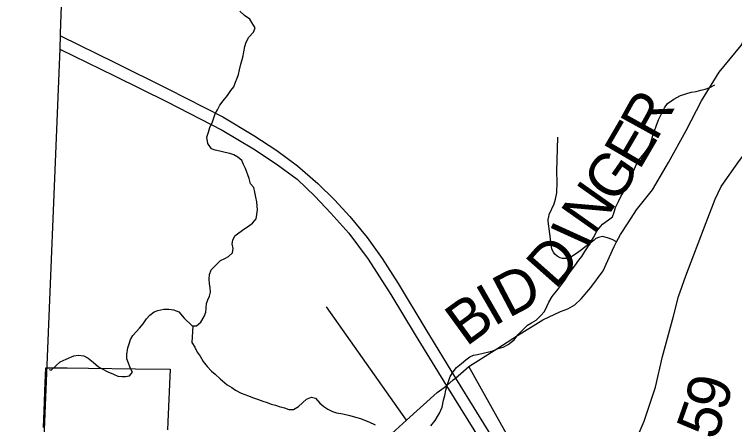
# Model space of a CAD drawing. Extents: x -7.5 to 26.5, y 3.5 to 25.5.
# Drawn here: x -5.222 to -4.268, y 22.72 to 23.263 of the extents above; entities that cross this region are included whole.
import ezdxf

# ---------------------------------------------------------------- set-up
doc = ezdxf.new("R2010")
doc.units = 0
for name, color, linetype in [('GM_X_Corporation', 7, 'Continuous'), ('GM_X_County_Road', 7, 'Continuous'), ('GM_X_County_Road_Text', 7, 'Continuous'), ('GM_X_Interstate_Route', 7, 'Continuous'), ('GM_X_Minor_River', 7, 'Continuous'), ('GM_X_Township_Road', 7, 'Continuous'), ('GM_X_US_Route', 7, 'Continuous')]:
    doc.layers.add(name, color=color, linetype=linetype)

msp = doc.modelspace()

# ---------------------------------------------------------------- linework, layer by layer
at = {"layer": 'GM_X_Corporation'}
for points in [[(-5.11944, 24.4), (-5.16153, 23.2384), (-5.16163, 23.23557), (-5.16227, 23.21794), (-5.18287, 22.71291), (-5.18115, 22.65086), (-5.18095, 22.62635), (-5.18249, 22.6005), (-5.18755, 22.52017), (-5.1934, 22.40363), (-5.2001, 22.30807), (-5.20396, 22.23332), (-5.20585, 22.15811), (-5.20891, 22.08209), (-5.21025, 22.04321), (-5.22035, 21.76062), (-5.22232, 21.69113)], [(-5.11944, 24.4), (-5.16153, 23.2384), (-5.16163, 23.23557), (-5.16227, 23.21794), (-5.18287, 22.71291), (-5.18115, 22.65086), (-5.18095, 22.62635), (-5.18249, 22.6005), (-5.18755, 22.52017), (-5.1934, 22.40363), (-5.2001, 22.30807), (-5.20396, 22.23332), (-5.20585, 22.15811), (-5.20891, 22.08209), (-5.21025, 22.04321), (-5.22035, 21.76062), (-5.22232, 21.69113)], [(-5.18393, 22.71585), (-5.18262, 22.74934), (-5.18204, 22.76439), (-5.18083, 22.79519), (-5.18023, 22.79518), (-5.17422, 22.79511), (-5.15254, 22.79484), (-5.12427, 22.79452), (-5.062, 22.79358), (-5.01576, 22.79314), (-5.01877, 22.72359), (-5.01924, 22.71283)]]:
    msp.add_lwpolyline(points, dxfattribs=at)
at = {"layer": 'GM_X_County_Road'}
for points in [[(-4.35566, 23.06728), (-4.33182, 23.10949), (-4.31153, 23.1487), (-4.28827, 23.18666), (-4.25921, 23.22223), (-4.25274, 23.23245), (-4.24549, 23.24501), (-4.23902, 23.26132), (-4.2197, 23.33347), (-4.21138, 23.35417), (-4.16498, 23.44964), (-4.15463, 23.4697), (-4.14803, 23.482), (-4.13664, 23.49921), (-4.12719, 23.50957), (-4.11734, 23.51788), (-4.09082, 23.53999), (-4.07435, 23.55822), (-4.06894, 23.57118), (-4.0648, 23.58322)], [(-4.44203, 22.60628), (-4.43341, 22.61893), (-4.41759, 22.654), (-4.3877, 22.72414), (-4.37246, 22.76927), (-4.36327, 22.81009), (-4.34875, 22.86326), (-4.342, 22.88942), (-4.33265, 22.91688), (-4.30534, 22.98745), (-4.29356, 23.01849), (-4.2858, 23.03516), (-4.26137, 23.06994), (-4.23664, 23.10214), (-4.22148, 23.12103), (-4.20941, 23.13189), (-4.1964, 23.1423), (-4.17513, 23.1597), (-4.15717, 23.17522), (-4.14294, 23.19218), (-4.12195, 23.21934), (-4.10744, 23.23745), (-4.0945, 23.25304), (-4.0327, 23.32822)], [(-4.61988, 22.7966), (-4.58176, 22.82124), (-4.55574, 22.83768), (-4.522, 22.85878), (-4.49876, 22.86957), (-4.48876, 22.87317), (-4.47953, 22.87867), (-4.47105, 22.8863), (-4.45841, 22.90149), (-4.44197, 22.92337), (-4.42755, 22.95596), (-4.4242, 22.96217), (-4.41897, 22.97188), (-4.40883, 22.9873), (-4.39764, 23.00434), (-4.37658, 23.03085), (-4.35864, 23.062), (-4.35566, 23.06728)], [(-4.64066, 22.77908), (-4.63785, 22.78145), (-4.61988, 22.7966)], [(-4.46159, 22.59567), (-4.49215, 22.60045), (-4.50619, 22.61232), (-4.56416, 22.69633), (-4.61988, 22.7966)], [(-4.81284, 22.52175), (-4.80803, 22.53338), (-4.80786, 22.54456), (-4.80806, 22.58647), (-4.80365, 22.61677), (-4.78984, 22.63267), (-4.76569, 22.66305), (-4.75141, 22.68158), (-4.70268, 22.72547), (-4.66184, 22.76227), (-4.6498, 22.77137), (-4.64066, 22.77908)]]:
    msp.add_lwpolyline(points, dxfattribs=at)
at = {"layer": 'GM_X_Interstate_Route'}
for points in [[(-5.1614, 23.23505), (-5.08921, 23.19954), (-5.01903, 23.16488), (-4.94621, 23.1276), (-4.90498, 23.10303), (-4.87471, 23.08285), (-4.84705, 23.0627), (-4.8203, 23.03934), (-4.79814, 23.01763), (-4.77797, 22.9957), (-4.75472, 22.96762), (-4.73498, 22.93977), (-4.71392, 22.90687), (-4.67707, 22.84589), (-4.63785, 22.78145), (-4.59132, 22.70618)], [(-5.16203, 23.21742), (-5.08985, 23.18191), (-5.01967, 23.14725), (-4.94685, 23.10997), (-4.90562, 23.0854), (-4.87535, 23.06522), (-4.84769, 23.04507), (-4.82403, 23.02267), (-4.80297, 22.99986), (-4.77928, 22.97354), (-4.7534, 22.93889), (-4.72357, 22.89239), (-4.69111, 22.83888), (-4.6498, 22.77137), (-4.60338, 22.69631), (-4.57048, 22.64192), (-4.5253, 22.56998), (-4.48845, 22.5169), (-4.45643, 22.47698), (-4.42178, 22.43794), (-4.38537, 22.39934), (-4.34896, 22.36293), (-4.18465, 22.20792)]]:
    msp.add_lwpolyline(points, dxfattribs=at)
at = {"layer": 'GM_X_Minor_River'}
for points in [[(-4.93162, 23.1675), (-4.92915, 23.17349), (-4.92709, 23.17875), (-4.92542, 23.18363), (-4.92409, 23.18966), (-4.92234, 23.19758), (-4.92063, 23.2036), (-4.91934, 23.20849), (-4.91842, 23.21378), (-4.91707, 23.22057), (-4.91537, 23.22659), (-4.91174, 23.23331), (-4.90545, 23.23995), (-4.90338, 23.24557), (-4.90627, 23.2506), (-4.91027, 23.25679), (-4.91735, 23.26195), (-4.92366, 23.26746)], [(-5.17625, 22.79288), (-5.17363, 22.79198), (-5.16736, 22.79786), (-5.1615, 22.80299), (-5.15378, 22.80655), (-5.14375, 22.8108), (-5.13801, 22.81176), (-5.13043, 22.81077), (-5.12442, 22.80793), (-5.11774, 22.80241), (-5.11069, 22.79612), (-5.10582, 22.79369), (-5.0987, 22.78968), (-5.09119, 22.78641), (-5.08517, 22.78395), (-5.07986, 22.7834), (-5.0749, 22.78363), (-5.06994, 22.78424), (-5.06597, 22.78943), (-5.06886, 22.79483), (-5.07132, 22.80136), (-5.07345, 22.80674), (-5.07326, 22.81281), (-5.07186, 22.82149), (-5.07018, 22.82675), (-5.06848, 22.83239), (-5.06527, 22.83799), (-5.06094, 22.84279), (-5.05661, 22.84759), (-5.05187, 22.85314), (-5.0471, 22.85982), (-5.04276, 22.865), (-5.03731, 22.86901), (-5.03229, 22.87113), (-5.02425, 22.87278), (-5.01777, 22.87296), (-5.01133, 22.87201), (-5.00456, 22.86914), (-4.9972, 22.86095), (-4.98684, 22.85076), (-4.98114, 22.85058), (-4.97529, 22.85534), (-4.97086, 22.86317), (-4.96879, 22.8688), (-4.96825, 22.8741), (-4.96769, 22.88015), (-4.96601, 22.88504), (-4.96358, 22.8899), (-4.96228, 22.89517), (-4.96286, 22.90126), (-4.96385, 22.90622), (-4.96404, 22.91268), (-4.96386, 22.91875), (-4.96177, 22.92476), (-4.9547, 22.93213), (-4.94921, 22.93728), (-4.94343, 22.93976), (-4.93839, 22.94264), (-4.9333, 22.94741), (-4.93237, 22.95308), (-4.9337, 22.95919), (-4.9328, 22.9641), (-4.93034, 22.96972), (-4.92488, 22.9741), (-4.9171, 22.97956), (-4.91205, 22.98282), (-4.9066, 22.98682), (-4.90187, 22.99237), (-4.90094, 22.99804), (-4.90036, 23.00447), (-4.90059, 23.00941), (-4.90118, 23.01512), (-4.90214, 23.02123), (-4.90347, 23.02772), (-4.90519, 23.03385), (-4.90922, 23.0389), (-4.9113, 23.0458), (-4.91623, 23.05923), (-4.91874, 23.06424), (-4.92086, 23.06963), (-4.92643, 23.07435), (-4.93129, 23.07716), (-4.93695, 23.07885), (-4.94299, 23.08055), (-4.95018, 23.08191), (-4.95623, 23.08324), (-4.96112, 23.08529), (-4.96586, 23.09226), (-4.96713, 23.10065), (-4.96502, 23.10742), (-4.96332, 23.11344), (-4.95967, 23.12092), (-4.9563, 23.13144), (-4.95309, 23.13704), (-4.95025, 23.14302), (-4.9455, 23.14895), (-4.93996, 23.15599), (-4.93558, 23.16231), (-4.93162, 23.1675)], [(-4.44295, 22.98546), (-4.43517, 22.99091), (-4.42973, 22.99492), (-4.42725, 23.00129), (-4.42555, 23.00731), (-4.42187, 23.01555), (-4.41863, 23.0219), (-4.41463, 23.02861), (-4.41179, 23.03421), (-4.40935, 23.03945), (-4.40766, 23.04509), (-4.40481, 23.05108), (-4.4016, 23.05667), (-4.39916, 23.06191), (-4.3967, 23.06753), (-4.39194, 23.07383), (-4.3876, 23.07901), (-4.38364, 23.0842), (-4.38044, 23.08904), (-4.37793, 23.09655), (-4.37622, 23.10295), (-4.37413, 23.10896), (-4.37166, 23.11534), (-4.36874, 23.1236), (-4.36429, 23.13257), (-4.36065, 23.13967), (-4.35667, 23.14524), (-4.3485, 23.15106), (-4.33961, 23.15572), (-4.33268, 23.15816), (-4.32538, 23.16021), (-4.31888, 23.16115), (-4.31274, 23.16286), (-4.30699, 23.1642), (-4.30084, 23.16629), (-4.29426, 23.16988)], [(-4.67029, 22.71805), (-4.66475, 22.72509), (-4.66155, 22.73031), (-4.65874, 22.73515), (-4.65546, 22.74302), (-4.65366, 22.75208), (-4.65195, 22.75848), (-4.6506, 22.76527), (-4.64888, 22.77167), (-4.64677, 22.77843), (-4.64471, 22.78368), (-4.64073, 22.78963), (-4.63636, 22.79557), (-4.62973, 22.80068), (-4.62426, 22.80545), (-4.61881, 22.80945), (-4.6138, 22.81158), (-4.60844, 22.81255), (-4.60116, 22.81422), (-4.59348, 22.81626), (-4.58811, 22.81762), (-4.58117, 22.82044), (-4.57464, 22.82252), (-4.56807, 22.82573), (-4.55989, 22.83193), (-4.55512, 22.83862), (-4.54884, 22.84488), (-4.54216, 22.8515), (-4.53712, 22.85476), (-4.53093, 22.85799), (-4.52465, 22.86424), (-4.51991, 22.86979), (-4.51668, 22.87614), (-4.51383, 22.88213), (-4.50942, 22.88958), (-4.50229, 22.89885), (-4.49555, 22.90775), (-4.49198, 22.91258), (-4.48797, 22.91929), (-4.47965, 22.93004), (-4.4741, 22.93746), (-4.47051, 22.94266), (-4.46652, 22.94899), (-4.46292, 22.95457), (-4.4589, 22.96166), (-4.45451, 22.96835), (-4.45127, 22.97471), (-4.4473, 22.98028), (-4.44295, 22.98546)], [(-4.98585, 22.85073), (-4.98714, 22.82837), (-4.98313, 22.82256), (-4.97991, 22.81563), (-4.97625, 22.81058), (-4.97229, 22.80325), (-4.96677, 22.79663), (-4.96124, 22.79076), (-4.95604, 22.78643), (-4.94975, 22.78054), (-4.94047, 22.77266), (-4.93411, 22.76905), (-4.92926, 22.76549), (-4.92177, 22.76146), (-4.91198, 22.75774), (-4.90672, 22.75569), (-4.89993, 22.75358), (-4.89316, 22.75071), (-4.88712, 22.74901), (-4.88186, 22.74695), (-4.87618, 22.74564), (-4.87129, 22.74397), (-4.86449, 22.74186), (-4.85847, 22.73978), (-4.85237, 22.73997), (-4.84579, 22.74356), (-4.84068, 22.74872), (-4.83521, 22.75349), (-4.82867, 22.75594), (-4.82338, 22.75464), (-4.81747, 22.74838), (-4.81229, 22.74367), (-4.80706, 22.7401), (-4.80068, 22.73724), (-4.7954, 22.73556), (-4.78707, 22.73417), (-4.77799, 22.73199), (-4.77006, 22.72985), (-4.76365, 22.72775), (-4.75839, 22.72569), (-4.75275, 22.72324), (-4.7441, 22.71956)]]:
    msp.add_lwpolyline(points, dxfattribs=at)
at = {"layer": 'GM_X_Township_Road'}
msp.add_line((-4.70268, 22.72547), (-4.80881, 22.87562), dxfattribs=at)
msp.add_lwpolyline([(-4.4242, 22.96217), (-4.43031, 22.96523), (-4.43615, 22.96738), (-4.44291, 22.96891), (-4.44844, 22.96768), (-4.45182, 22.96645), (-4.45397, 22.9643), (-4.47426, 22.94893), (-4.48409, 22.94187), (-4.48717, 22.94094), (-4.49086, 22.94002), (-4.49393, 22.93971), (-4.49608, 22.93971), (-4.49885, 22.94064), (-4.50284, 22.94309), (-4.50622, 22.94555), (-4.50807, 22.94832), (-4.51022, 22.95232), (-4.51053, 22.9557), (-4.51483, 22.98951), (-4.51483, 22.99289), (-4.51422, 22.99473), (-4.5136, 22.99811), (-4.50715, 23.01225), (-4.50592, 23.01533), (-4.5053, 23.01871), (-4.50346, 23.0267), (-4.50284, 23.04084), (-4.50346, 23.05498), (-4.50201, 23.10078)], dxfattribs=at)
at = {"layer": 'GM_X_US_Route'}
msp.add_lwpolyline([(-5.16203, 23.21742), (-5.08985, 23.18191), (-5.01967, 23.14725), (-4.94685, 23.10997), (-4.90562, 23.0854), (-4.87535, 23.06522), (-4.84769, 23.04507), (-4.82403, 23.02267), (-4.80297, 22.99986), (-4.77928, 22.97354), (-4.7534, 22.93889), (-4.72357, 22.89239), (-4.69111, 22.83888), (-4.6498, 22.77137), (-4.60338, 22.69631), (-4.57048, 22.64192), (-4.5253, 22.56998), (-4.48845, 22.5169), (-4.45643, 22.47698), (-4.42178, 22.43794), (-4.38537, 22.39934), (-4.34896, 22.36293), (-4.18465, 22.20792)], dxfattribs=at)

# ---------------------------------------------------------------- texts
at = {"layer": 'GM_X_County_Road_Text'}
for s, rotation, p in [('R', 61.09451, (-4.37201, 23.09367)), ('E', 59.74178, (-4.39415, 23.05568)), ('G', 55.28931, (-4.42521, 23.01051)), ('N', 54.80874, (-4.45432, 22.96923)), ('I', 65.57664, (-4.46257, 22.95043)), ('D', 48.50039, (-4.50572, 22.89752)), ('D', 27.73114, (-4.56758, 22.86045)), ('I', 30.02711, (-4.58726, 22.84906)), ('B', 36.06381, (-4.62365, 22.82245)), ('9', 75.65763, (-4.27954, 22.73586)), ('5', 70.50979, (-4.29284, 22.69753))]:
    msp.add_text(s, height=0.05682, rotation=rotation, dxfattribs=at).set_placement(p)

doc.saveas('drawing.dxf')
